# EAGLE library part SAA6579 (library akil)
RDS Demodulator demodulator decodes the mux signal to retrieve rds data
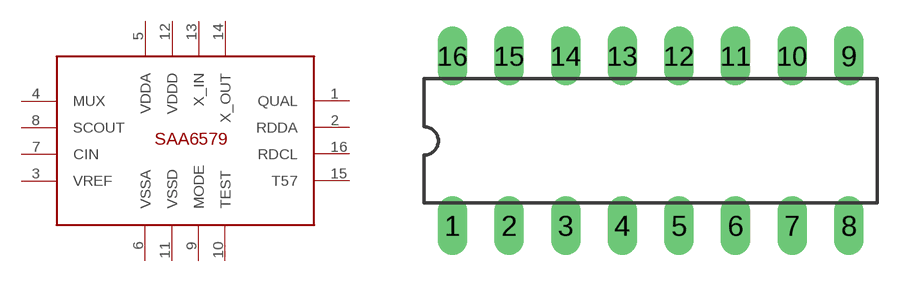
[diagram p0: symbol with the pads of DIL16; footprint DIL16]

Designator prefix -

## SAA6579  [DIL16]
1  QUAL
2  RDDA
3  VREF
4  MUX
5  VDDA
6  VSSA
7  CIN
8  SCOUT
9  MODE
10  TEST
11  VSSD
12  VDDD
13  X_IN
14  X_OUT
15  T57
16  RDCL

## Footprint DIL16 (pad centres in mm)
Dual Inline Package 16 PIN
drill 0.813 long: 1 -8.89,-2.54; 2 -6.35,-2.54; 3 -3.81,-2.54; 4 -1.27,-2.54; 5 1.27,-2.54; 6 3.81,-2.54; 7 6.35,-2.54; 8 8.89,-2.54; 9 8.89,5.08; 10 6.35,5.08; 11 3.81,5.08; 12 1.27,5.08; 13 -1.27,5.08; 14 -3.81,5.08; 15 -6.35,5.08; 16 -8.89,5.08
